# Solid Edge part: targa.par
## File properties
Author: Mac
Template: Normal.par
Last saved by: Mac
Revision: 6
Application: Solid Edge
Material: Epoxy, cast rigid
Face Style: White
Fill Style: ANSI34(Plastic)
Virtual Style: Shiny resin yellow
Coef. of Thermal Exp: 5.9e-05
Thermal Conductivity: 2.1
Specific Heat: 0.0
Modulus of Elasticity: 3102640650.0
Poission's Ratio: 0.37
Yield Stress: 65500191.5
Ultimate Stress: 0.0
Elongation: 0.0
Density: 1300,000 kg/m^3
Accuracy: 0,990
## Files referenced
..\Asm13.asm
=C:\Documents and Settings\Mac\Desktop\copy of paat2\Asm13.asm
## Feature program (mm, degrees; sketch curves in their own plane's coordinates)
sketch for "unnamed Protrusion 1" plane through (0, 0, 0) normal (0, 0, 1) x-axis (1, 0, 0)
  line (0.1262, 0) -> (-36.1823, 0)
  line (-36.1823, 25.8602) -> (-36.1823, 0)
  line (0.1262, 25.8602) -> (-36.1823, 25.8602)
  line (0.1262, 0) -> (0.1262, 25.8602)
extrude "unnamed Protrusion 1" add finite 24 along +normal
sketch for "unnamed Cutout 1" plane through (-10.6931, 0, 12) normal (0, -1, 0) x-axis (1, 0, 0)
  bspline degree 3 poles (13.6467, -9.8363) (4.591, -4.3985) (-3.6751, -0.4753) (-11.1515, 1.9332) knots 0 1 multiplicities 4 4
  arc centre (-11.1822, 1.838) radius 0.1 from (-11.1515, 1.9332) to (-11.1822, 1.938) ccw
  line (-11.1822, 1.938) -> (-15.7684, 1.938)
  arc centre (-15.7684, 1.838) radius 0.1 from (-15.824, 1.7549) to (-15.7684, 1.938) cw
  line (4.7033, -12) -> (-15.824, 1.7549)
  line (4.7033, -12) -> (13.7438, -12)
  line (13.7438, -10.0077) -> (13.7438, -12)
  arc centre (13.5438, -10.0077) radius 0.2 from (13.6467, -9.8363) to (13.7438, -10.0077) cw
extrude "unnamed Cutout 1" cut through along -normal
lofted cutout "unnamed LoftedCutout 1"
sketch for "unnamed Cutout 2" plane through (0.1262, 12.9311, 1.9135) normal (1, 0, 0) x-axis (0, 1, 0)
  line (-12.9311, 9.9118) -> (-12.9311, 11.5894)
  line (-12.9311, 11.5894) -> (10.6889, 11.5894)
  arc centre (10.6889, 9.3492) radius 2.2402 from (12.9291, 9.3492) to (10.6889, 11.5894) ccw
  line (12.9291, -1.9135) -> (12.9291, 9.3492)
  line (10.9291, -1.9135) -> (12.9291, -1.9135)
  line (10.9291, -1.9135) -> (10.9291, 8.911)
  arc centre (9.9283, 8.911) radius 1.0008 from (9.9283, 9.9118) to (10.9291, 8.911) cw
  line (9.9283, 9.9118) -> (-12.9311, 9.9118)
extrude "unnamed Cutout 2" cut through along -normal
sketch for "unnamed Cutout 3" plane through (0.1262, 24.8611, 1.9135) normal (1, 0, 0) x-axis (0, 1, 0)
  line (-1.1514, 12.0245) -> (-24.8611, 12.0245)
  arc centre (-1.1514, 9.874) radius 2.1504 from (-1.1514, 12.0245) to (0.999, 9.874) cw
  line (0.999, 1.9136) -> (0.999, 9.874)
extrude "unnamed Cutout 3" cut through along -normal
thinwall "Thinwall_1"  Thickness = 0.06 mm
body pattern "unnamed BodyPattern 1"
pattern "unnamed Pattern 1"
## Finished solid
Body 1: solid body, 48 faces, 132 edges, 88 vertices, 1 internal void.
  Faces by surface: plane 22, cylinder 12, offset 7, spline 6, swept 1
  Edges by curve: line 66, intersection 46, ellipse 8, spline 8, circle 2, curve on surface 2
Bounding box of the edges (mm; curved faces can reach further): 26.643 x 51.720 x 13.938, from (-26.5171, -25.8602, 0) to (0.1262, 25.8602, 13.938).
Cylindrical faces by radius (mm): R0.04 x2, R0.1 x2, R1.0008 x2, R1.0608 x2, R2.0904 x2, R2.1504 x2
Planar faces by outward normal: +x 2, +y 4, +z 4, -x 2, -y 4, -z 4, oblique 2
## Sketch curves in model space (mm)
line (-10.4346, 24.8478, 2.3392) -> (-10.4346, 25.0792, 2.3392)
spline (-10.4346, 25.0792, 2.3392) -> (-10.4346, 26.4394, 1.8152) -> (-10.4346, 27.0786, 0.5079)
line (-10.4346, 27.0786, -0.7025) -> (-10.4346, 27.0786, 0.5079)
line (-10.4346, 24.6638, -0.7025) -> (-10.4346, 27.0786, -0.7025)
line (-10.4346, 24.6638, 0) -> (-10.4346, 24.6638, -0.7025)
spline (-10.4346, 24.6638, 0) -> (-10.4346, 24.756, 1.1696) -> (-10.4346, 24.8478, 2.3392)
line (0.1262, 25.1874, -0.327) -> (0.1262, 25.1874, 0)
line (0.1262, 27.6135, -0.327) -> (0.1262, 25.1874, -0.327)
line (0.1262, 27.6135, 1.2235) -> (0.1262, 27.6135, -0.327)
arc centre (0.1262, 25.6191, 1.0533) radius 2.0016 from (0.1262, 27.6135, 1.2235) through (0.1262, 26.9277, 2.5679) to (0.1262, 25.617, 3.0549)
line (0.1262, 25.617, 3.0549) -> (0.1262, 25.3911, 3.0547)
line (0.1262, 25.3911, 3.0547) -> (0.1262, 25.1874, 0)
line (0.1262, 0, 0) -> (-5.9898, 0, 0)
line (0.1262, 0, 3.8271) -> (0.1262, 0, 0)
spline (0.1262, 0, 3.8271) -> (-9.6533, 0, 9.0012) -> (-18.7506, 0, 12.8665)
line (-21.5125, 0, 12.8665) -> (-18.7506, 0, 12.8665)
line (-21.5125, 0, 12.8665) -> (-21.5125, 0, 10.4014)
line (-21.5125, 0, 10.4014) -> (-5.9898, 0, 0)
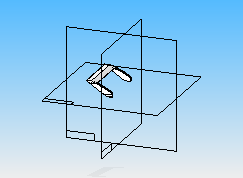
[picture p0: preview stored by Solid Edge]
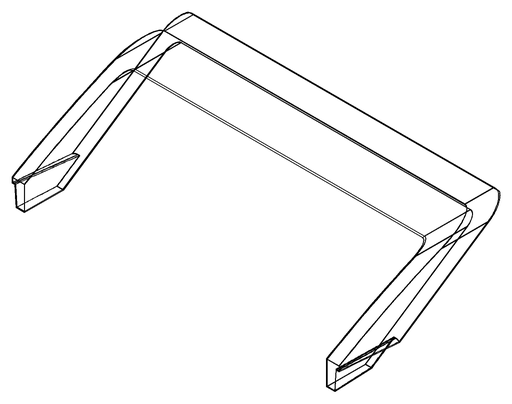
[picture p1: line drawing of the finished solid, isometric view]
